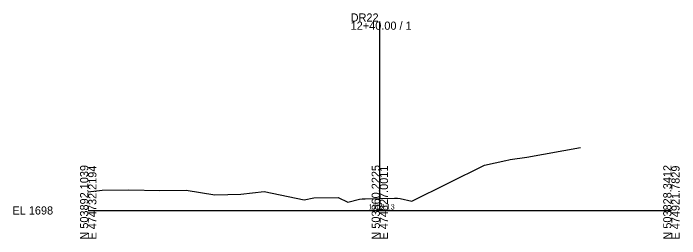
# Model space of a CAD drawing. Extents: x -26 to 1203, y -10 to 9633.
# Drawn here: x -25.7 to 202.8, y 5990.3 to 6067.7 of the extents above; entities that cross this region are included whole.
import ezdxf

# ---------------------------------------------------------------- set-up
doc = ezdxf.new("R2010")
doc.units = 0
for name, color, linetype in [('Exist Cross Section Cell', 7, 'Continuous'), ('Exist XS Center Line Elevation Label', 7, 'Continuous'), ('Exist XS Ground Line', 7, 'Continuous'), ('Scratch_Level_5', 7, 'Continuous')]:
    doc.layers.add(name, color=color, linetype=linetype)

msp = doc.modelspace()

# ---------------------------------------------------------------- linework, layer by layer
at = {"layer": 'Exist Cross Section Cell'}
for p, q in [((100, 6000), (100, 6064.84)), ((0, 6000), (100, 6000)), ((100, 6000), (200, 6000))]:
    msp.add_line(p, q, dxfattribs=at)
at = {"layer": 'Exist XS Ground Line'}
msp.add_lwpolyline([(0, 6006.38), (4.72, 6006.99), (13.87, 6007.09), (24.57, 6006.83), (33.55, 6007), (43.41, 6005.33), (52.38, 6005.57), (60.34, 6006.51), (74.01, 6003.69), (77.32, 6004.39), (85.77, 6004.48), (89, 6002.87), (93, 6003.87), (93.98, 6003.94), (95, 6004.03), (100, 6004.13), (105, 6004.23), (106.02, 6004.18), (107, 6004.15), (111, 6003.15), (135.91, 6015.6), (143.26, 6017.18), (144.23, 6017.39), (144.76, 6017.51), (150.43, 6018.29), (168.83, 6021.61)], dxfattribs=at)
at = {"layer": 'Scratch_Level_5'}
msp.add_lwpolyline([(0, 6006.38), (4.72, 6006.99), (13.87, 6007.09), (24.57, 6006.83), (33.55, 6007), (43.41, 6005.33), (52.38, 6005.57), (60.34, 6006.51), (74.01, 6003.69), (77.32, 6004.39), (85.77, 6004.48), (89, 6002.87), (93, 6003.87), (93.98, 6003.94), (95, 6004.03), (100, 6004.13), (105, 6004.23), (106.02, 6004.18), (107, 6004.15), (111, 6003.15), (135.91, 6015.6), (143.26, 6017.18), (144.23, 6017.39), (144.76, 6017.51), (150.43, 6018.29), (168.83, 6021.61)], dxfattribs=at)

# ---------------------------------------------------------------- texts
at = {"layer": 'Exist Cross Section Cell'}
for s, p in [('DR22', (90, 6064.84)), ('12+40.00 / 1', (90, 6062.04)), ('EL 1698', (-26, 5998.6))]:
    msp.add_text(s, height=2.8, dxfattribs=at).set_placement(p)
for s, p in [('N 503892.1039', (0, 5990)), ('E 474732.2194', (2.8, 5990)), ('N 503860.2225', (100, 5990)), ('E 474827.0011', (102.8, 5990)), ('N 503828.3412', (200, 5990)), ('E 474921.7829', (202.8, 5990))]:
    msp.add_text(s, height=2.8, rotation=90, dxfattribs=at).set_placement(p)
at = {"layer": 'Exist XS Center Line Elevation Label'}
msp.add_text('1702.13', height=1.8, dxfattribs=at).set_placement((96.11, 6000.33))

doc.saveas('drawing.dxf')
